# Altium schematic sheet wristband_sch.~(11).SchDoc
size A2
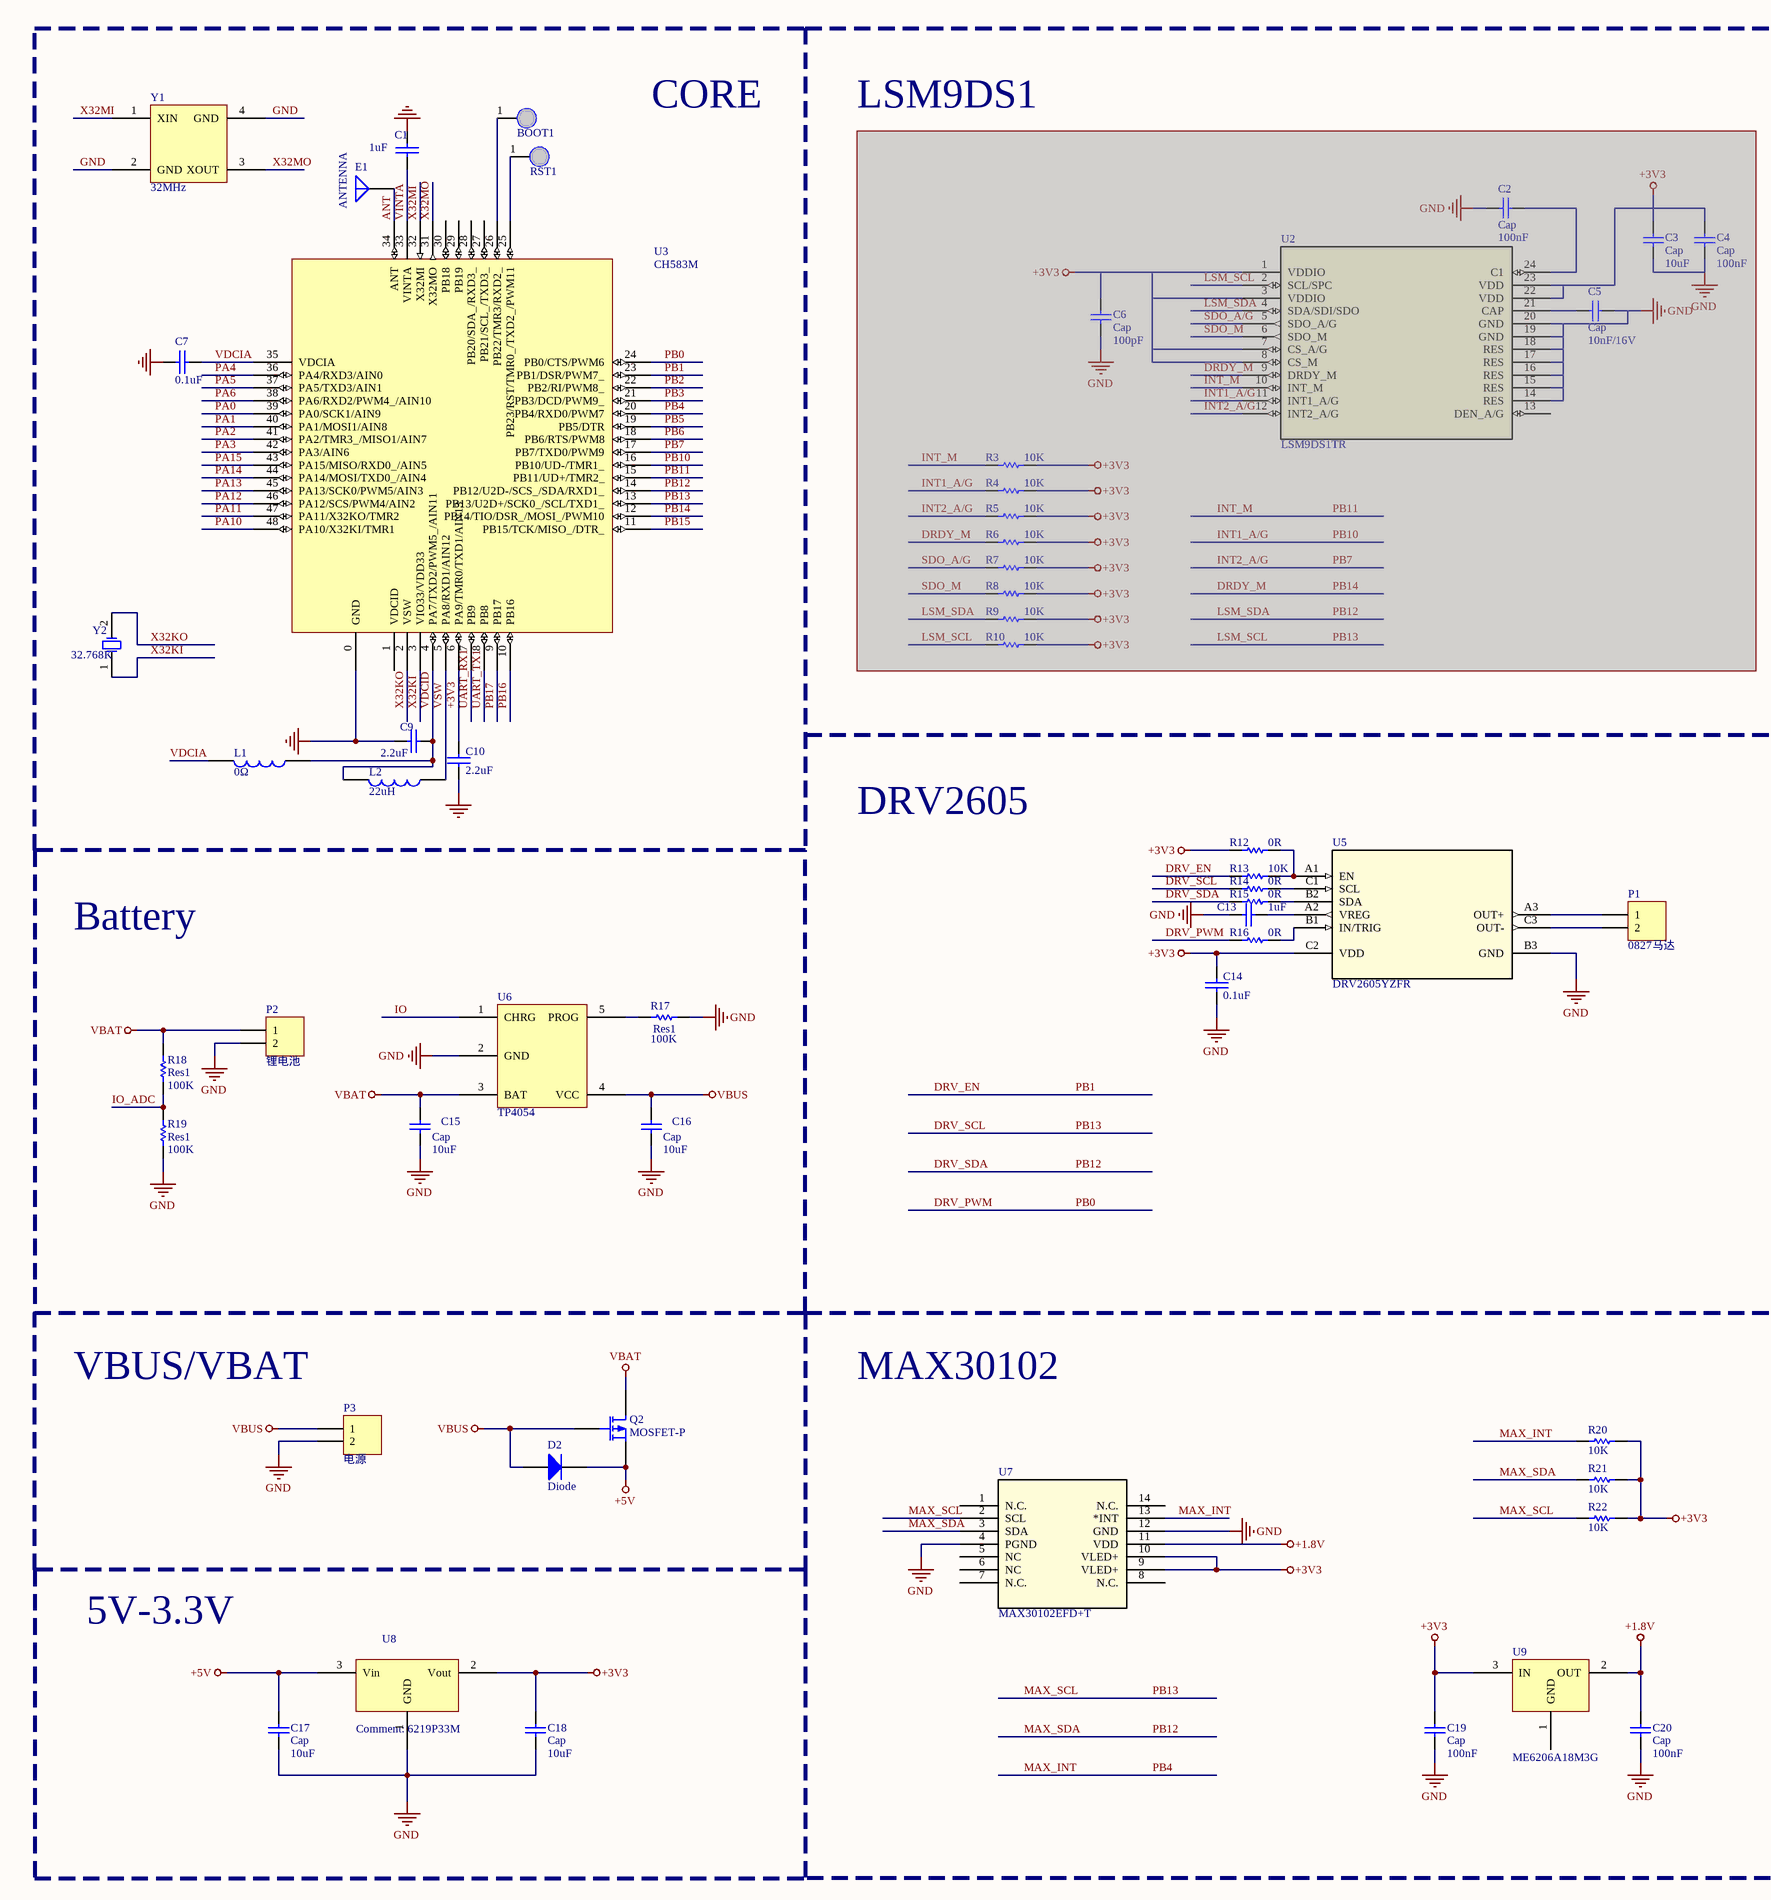
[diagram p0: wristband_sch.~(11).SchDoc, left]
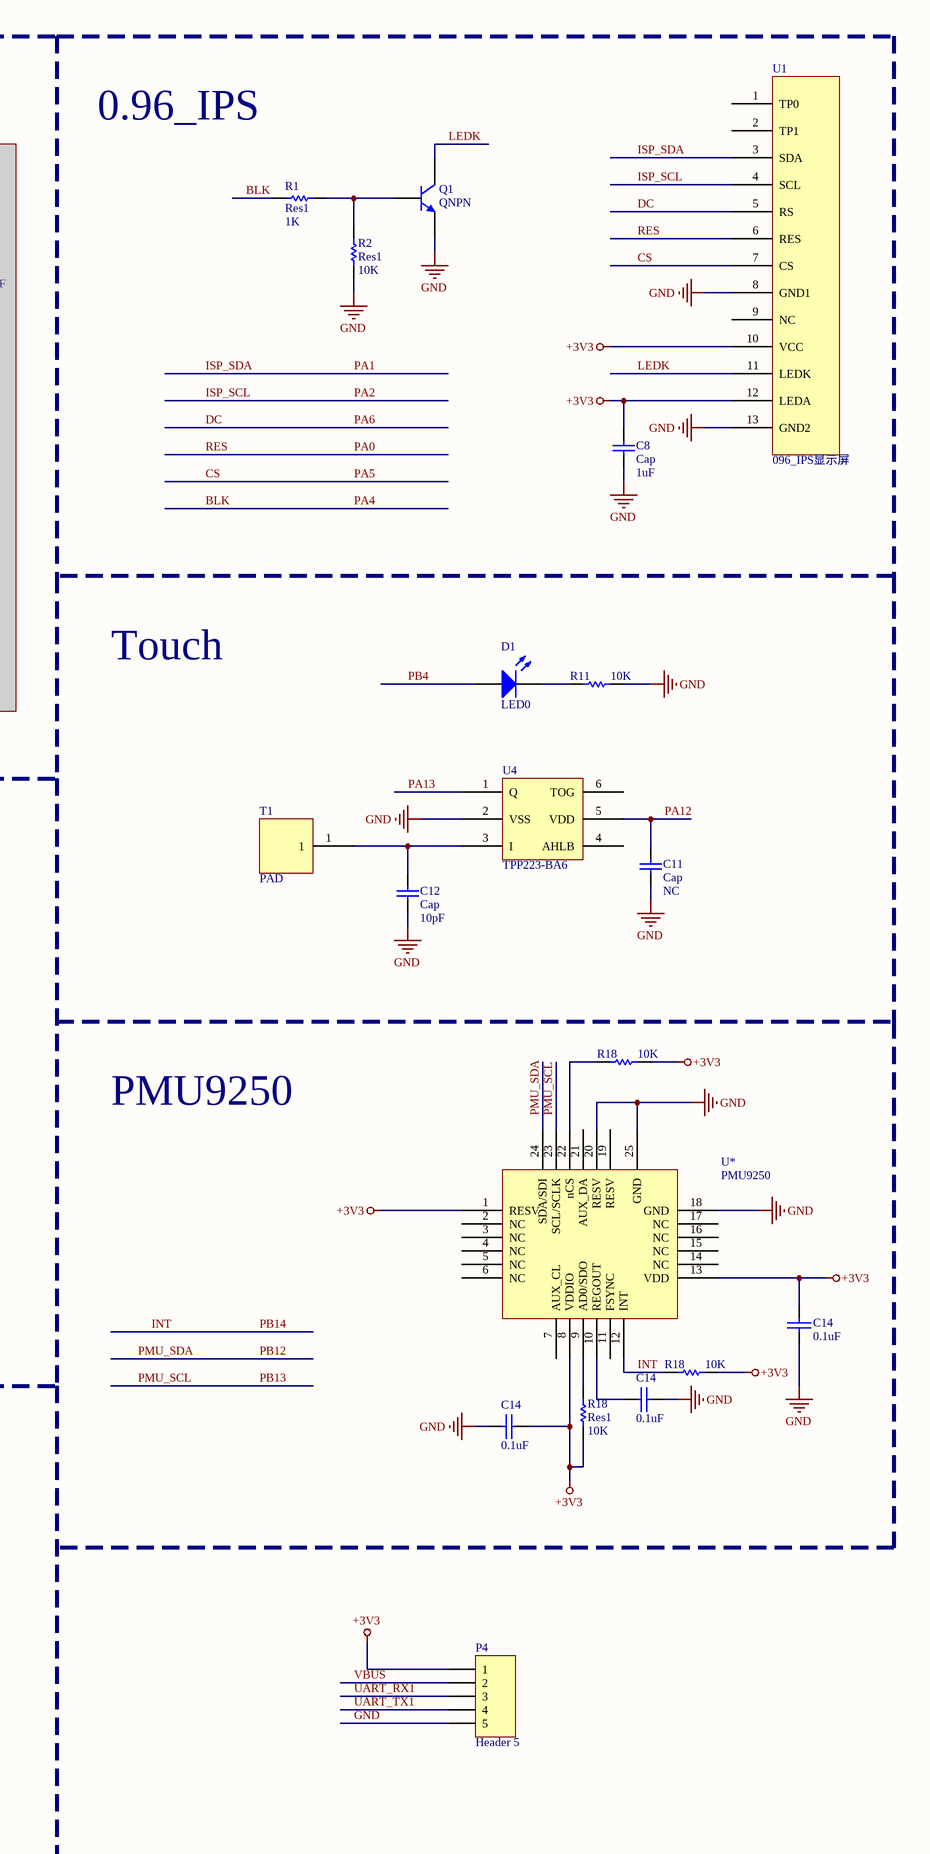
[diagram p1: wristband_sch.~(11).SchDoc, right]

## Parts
(Parts that share a designator on the sheet are numbered #1, #2 ... from top to bottom, then left to right.)
BOOT1  BOOT  [TESTPOINT1]  (value not drawn)
C1  1uF  [0402]
C2  Cap  value 100nF  [RAD-0.3]  (masked out: inside a compile mask, not in the netlist)
C3  Cap  value 10uF  [RAD-0.3]  (masked out: inside a compile mask, not in the netlist)
C4  Cap  value 100nF  [RAD-0.3]  (masked out: inside a compile mask, not in the netlist)
C5  Cap  value 10nF/16V  [RAD-0.3]  (masked out: inside a compile mask, not in the netlist)
C6  Cap  value 100pF  [RAD-0.3]  (masked out: inside a compile mask, not in the netlist)
C7  0.1uF  [0402]
C8  Cap  value 1uF  [RAD-0.3]
C9  2.2uF  [0402]
C10  2.2uF  [0402]
C11  Cap  value NC  [RAD-0.3]
C12  Cap  value 10pF  [RAD-0.3]
C13  1uF  [0402]
C14#1  0.1uF  [0402]
C14#2  0.1uF  [0402]
C14#3  0.1uF  [0402]
C14#4  0.1uF  [0402]
C15  Cap  value 10uF  [RAD-0.3]
C16  Cap  value 10uF  [RAD-0.3]
C17  Cap  value 10uF  [RAD-0.3]
C18  Cap  value 10uF  [RAD-0.3]
C19  Cap  value 100nF  [RAD-0.3]
C20  Cap  value 100nF  [RAD-0.3]
D1  LED0  [LED-0]
D2  Diode  [SMC]
E1  ANTENNA  [ANT-F-1-2.4G-1.6]
L1  0Ω  [0603]
L2  22uH  [L2.2]
P1  0827马达  [HDR1X2H]
P2  锂电池  [HDR1X2]
P3  电源  [HDR1X2]
P4  Header 5  [HDR1X5]
Q1  QNPN  [SOT-23B_N]
Q2  MOSFET-P  [E3]
R1  Res1  value 1K  [AXIAL-0.3]
R2  Res1  value 10K  [AXIAL-0.3]
R3  value 10K  [AXIAL-0.3]  (hidden comment: Res1)  (masked out: inside a compile mask, not in the netlist)
R4  value 10K  [AXIAL-0.3]  (hidden comment: Res1)  (masked out: inside a compile mask, not in the netlist)
R5  value 10K  [AXIAL-0.3]  (hidden comment: Res1)  (masked out: inside a compile mask, not in the netlist)
R6  value 10K  [AXIAL-0.3]  (hidden comment: Res1)  (masked out: inside a compile mask, not in the netlist)
R7  value 10K  [AXIAL-0.3]  (hidden comment: Res1)  (masked out: inside a compile mask, not in the netlist)
R8  value 10K  [AXIAL-0.3]  (hidden comment: Res1)  (masked out: inside a compile mask, not in the netlist)
R9  value 10K  [AXIAL-0.3]  (hidden comment: Res1)  (masked out: inside a compile mask, not in the netlist)
R10  value 10K  [AXIAL-0.3]  (hidden comment: Res1)  (masked out: inside a compile mask, not in the netlist)
R11  value 10K  [AXIAL-0.3]  (hidden comment: Res1)
R12  value 0R  [AXIAL-0.3]  (hidden comment: Res1)
R13  value 10K  [AXIAL-0.3]  (hidden comment: Res1)
R14  value 0R  [AXIAL-0.3]  (hidden comment: Res1)
R15  value 0R  [AXIAL-0.3]  (hidden comment: Res1)
R16  value 0R  [AXIAL-0.3]  (hidden comment: Res1)
R17  Res1  value 100K  [AXIAL-0.3]
R18#1  value 10K  [AXIAL-0.3]  (hidden comment: Res1)
R18#2  Res1  value 100K  [AXIAL-0.3]
R18#3  value 10K  [AXIAL-0.3]  (hidden comment: Res1)
R18#4  Res1  value 10K  [AXIAL-0.3]
R19  Res1  value 100K  [AXIAL-0.3]
R20  value 10K  [AXIAL-0.3]  (hidden comment: Res1)
R21  value 10K  [AXIAL-0.3]  (hidden comment: Res1)
R22  value 10K  [AXIAL-0.3]  (hidden comment: Res1)
RST1  BOOT  [TESTPOINT1]  (value not drawn)
T1  PAD
U1  096_IPS显示屏
U2  LSM9DS1TR  [LGA-24_3X3P5X1_STM]  (masked out: inside a compile mask, not in the netlist)
U3  CH583M  [QFN48_5X5]
U4  TPP223-BA6
U5  DRV2605YZFR  [YZF9]
U6  TP4054
U7  MAX30102EFD+T  [21-1048_F143A5+1_MXM]
U8  6219P33M  [SOT-23]
U9  ME6206A18M3G
U*  PMU9250
Y1  32MHz  [3225]
Y2  32.768K  [fc-135]

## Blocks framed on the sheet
CORE: BOOT1 C1 C7 C9 C10 E1 L1 L2 RST1 U3 Y1 Y2

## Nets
+1.8V: C20.1 U7.11(VDD) U9.2(OUT)
+3V3: C8.1 C10.2 C14#1.2 C14#2.2 C14#4.2 C18.1 C19.1 P4.1 R12.1 R18#1.2 R18#3.2 R18#4.2 R20.1 R21.1 R22.1 U1.10(VCC) U1.12(LEDA) U3.6(PA9/TMR0/TXD1/AIN13) U5.C2(VDD) U7.9(VLED+) U7.10(VLED+) U8.2(Vout) U9.3(IN) U*.1(RESV) U*.8(VDDIO) U*.13(VDD)
+5V: C17.1 D2.2(K) Q2.3(S) U8.3(Vin)
GND: C1.2 C7.2 C8.2 C9.1 C10.1 C11.2 C12.2 C13.1 C14#1.1 C14#2.1 C14#3.2 C14#4.1 C15.1 C16.1 C17.2 C18.2 C19.2 C20.2 P2.2 P3.2 P4.5 Q1.3(E) R2.2 R11.2 R17.2 R19.1 U1.8(GND1) U1.13(GND2) U3.0(GND) U4.2(VSS) U5.B3(GND) U6.2(GND) U7.4(PGND) U7.12(GND) U8.1(GND) U*.18(GND) U*.20(RESV) U*.25(GND) Y1.2(GND) Y1.4(GND)
VBAT: C15.2 P2.1 Q2.1(D) R18#2.1 U6.3(BAT)
VBUS: C16.2 D2.1(A) P3.1 P4.2 Q2.2(G) U6.4(VCC)
ANT: E1.1(A) U3.34(ANT)
BLK: R1.2 U3.36(PA4/RXD3/AIN0)  [also labelled PA4]
CS: U1.7(CS) U3.37(PA5/TXD3/AIN1)  [also labelled PA5]
DC: U1.5(RS) U3.38(PA6/RXD2/PWM4_/AIN10)  [also labelled PA6]
DRV_EN: R13.1 U3.23(PB1/DSR/PWM7_)  [also labelled PB1]
DRV_PWM: R16.1 U3.24(PB0/CTS/PWM6)  [also labelled PB0]
DRV_SCL: R14.1 R22.2 U3.13(PB13/U2D+/SCK0_/SCL/TXD1_) U7.2(SCL) U*.23(SCL/SCLK)  [also labelled MAX_SCL, PB13, PMU_SCL]
DRV_SDA: R15.1 R21.2 U3.14(PB12/U2D-/SCS_/SDA/RXD1_) U7.3(SDA) U*.24(SDA/SDI)  [also labelled MAX_SDA, PB12, PMU_SDA]
INT: R18#3.1 U3.12(PB14/TIO/DSR_/MOSI_/PWM10) U*.12(INT)  [also labelled PB14]
IO: U6.1(CHRG)
IO_ADC: R18#2.2 R19.2
ISP_SCL: U1.4(SCL) U3.41(PA2/TMR3_/MISO1/AIN7)  [also labelled PA2]
ISP_SDA: U1.3(SDA) U3.40(PA1/MOSI1/AIN8)  [also labelled PA1]
LEDK: Q1.1(C) U1.11(LEDK)
MAX_INT: D1.1(A) R20.2 U3.20(PB4/RXD0/PWM7) U7.13(*INT)  [also labelled PB4]
PA0: U1.6(RES) U3.39(PA0/SCK1/AIN9)  [also labelled RES]
PA3: U3.42(PA3/AIN6)
PA10: U3.48(PA10/X32KI/TMR1)
PA11: U3.47(PA11/X32KO/TMR2)
PA12: C11.1 U3.46(PA12/SCS/PWM4/AIN2) U4.5(VDD)
PA13: U3.45(PA13/SCK0/PWM5/AIN3) U4.1(Q)
PA14: U3.44(PA14/MOSI/TXD0_/AIN4)
PA15: U3.43(PA15/MISO/RXD0_/AIN5)
PB2: U3.22(PB2/RI/PWM8_)
PB3: U3.21(PB3/DCD/PWM9_)
PB5: U3.19(PB5/DTR)
PB6: U3.18(PB6/RTS/PWM8)
PB7: U3.17(PB7/TXD0/PWM9)
PB10: U3.16(PB10/UD-/TMR1_)
PB11: U3.15(PB11/UD+/TMR2_)
PB15: U3.11(PB15/TCK/MISO_/DTR_)
PB16: U3.10(PB16)
PB17: U3.9(PB17)
UART_RX1: P4.3 U3.7(PB9)
UART_TX1: P4.4 U3.8(PB8)
VDCIA: C7.1 L1.2 U3.35(VDCIA)
VDCID: C9.2 L1.1 L2.2 U3.4(PA7/TXD2/PWM5_/AIN11)
VINTA: C1.1 U3.33(VINTA)
VSW: L2.1 U3.5(PA8/RXD1/AIN12)
X32KI: U3.3(VIO33/VDD33) Y2.1(OSC1)
X32KO: U3.2(VSW) Y2.2(OSC2)
X32MI: U3.32(X32MI) Y1.1(XIN)
X32MO: U3.31(X32MO) Y1.3(XOUT)
NetBOOT1_1: BOOT1.1 U3.26(PB22/TMR3/RXD2_)
NetC12_1: C12.1 T1.1 U4.3(I)
NetC13_2: C13.2 U5.A2(VREG)
NetC14#3_1: C14#3.1 U*.10(REGOUT)
NetD1_2: D1.2(K) R11.1
NetP1_1: P1.1 U5.A3(OUT+)
NetP1_2: P1.2 U5.C3(OUT-)
NetQ1_2: Q1.2(B) R1.1 R2.1
NetR12_2: R12.2 R13.2 U5.A1(EN)
NetR14_2: R14.2 U5.C1(SCL)
NetR15_2: R15.2 U5.B2(SDA)
NetR16_2: R16.2 U5.B1(IN/TRIG)
NetR17_1: R17.1 U6.5(PROG)
NetR18#1_1: R18#1.1 U*.22(nCS)
NetR18#4_1: R18#4.1 U*.9(AD0/SDO)
NetRST1_1: RST1.1 U3.25(PB23/RST/TMR0_/TXD2_/PWM11)

Not connected (* = marked no-connect by the designer): U1 1(TP0) 2(TP1) 9(NC); U3 1(VDCID) 27(PB21/SCL_/TXD3_) 28(PB20/SDA_/RXD3_) 29(PB19) 30(PB18); U4 4(AHLB) 6(TOG); U7 1(N.C.) 5(NC) 6(NC) 7(N.C.) 8(N.C.) 14(N.C.); U9 1(GND); U* 2(NC) 3(NC) 4(NC) 5(NC) 6(NC) 7(AUX_CL) 11(FSYNC) 14(NC) 15(NC) 16(NC) 17(NC) 19(RESV) 21(AUX_DA)

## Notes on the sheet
- LSM9DS1
- 0.96_IPS
- Touch
- DRV2605
- Battery
- PMU9250
- VBUS/VBAT
- MAX30102
- 5V-3.3V

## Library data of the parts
BOOT1 RST1 = PAD 1.2MM
C1 C7 C9 C10 C13 C14#1-C14#4 = CAP: Capacitor
C2-C6 C8 C11 C12 C15-C20 = Cap: Capacitor
D1 = LED0: Typical INFRARED GaAs LED
D2 = Diode: Default Diode
E1 = ANTENNA: Generic Antenna
L1 L2 = INDUCTOR
P1 = Header 2H: Header, 2-Pin, Right Angle
P2 P3 = Header 2: Header, 2-Pin
P4 = Header 5: Header, 5-Pin
Q1 = QNPN: NPN Bipolar Transistor
Q2 = MOSFET-P: P-Channel MOSFET
R1-R17 R18#1-R18#4 R19-R22 = Res1: Resistor
U1 = Component_1
U2 = LSM9DS1TR: No Description Available; Vendor: STMicroelectronics; Built_By: EMA_Jessica; SourceLibrary: Updates_to_database_2020-11-03
U3 = CH583M: RISC-V MCU with BLE/2*USB/ADC/PWM/SPI/I2C/4*UART
U5 = DRV2605YZFR: No Description Available; Vendor: TEXAS INSTRUMENTS
U7 = MAX30102EFD+T: No Description Available; SourceLibrary: Update_to_database_2021-01-29; Built_By: EMA_UL_Team; Vendor: Maxim Integrated Products
Y1 = 晶体
Y2 = XTAL: Crystal Oscillator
